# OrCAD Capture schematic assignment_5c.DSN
size A3
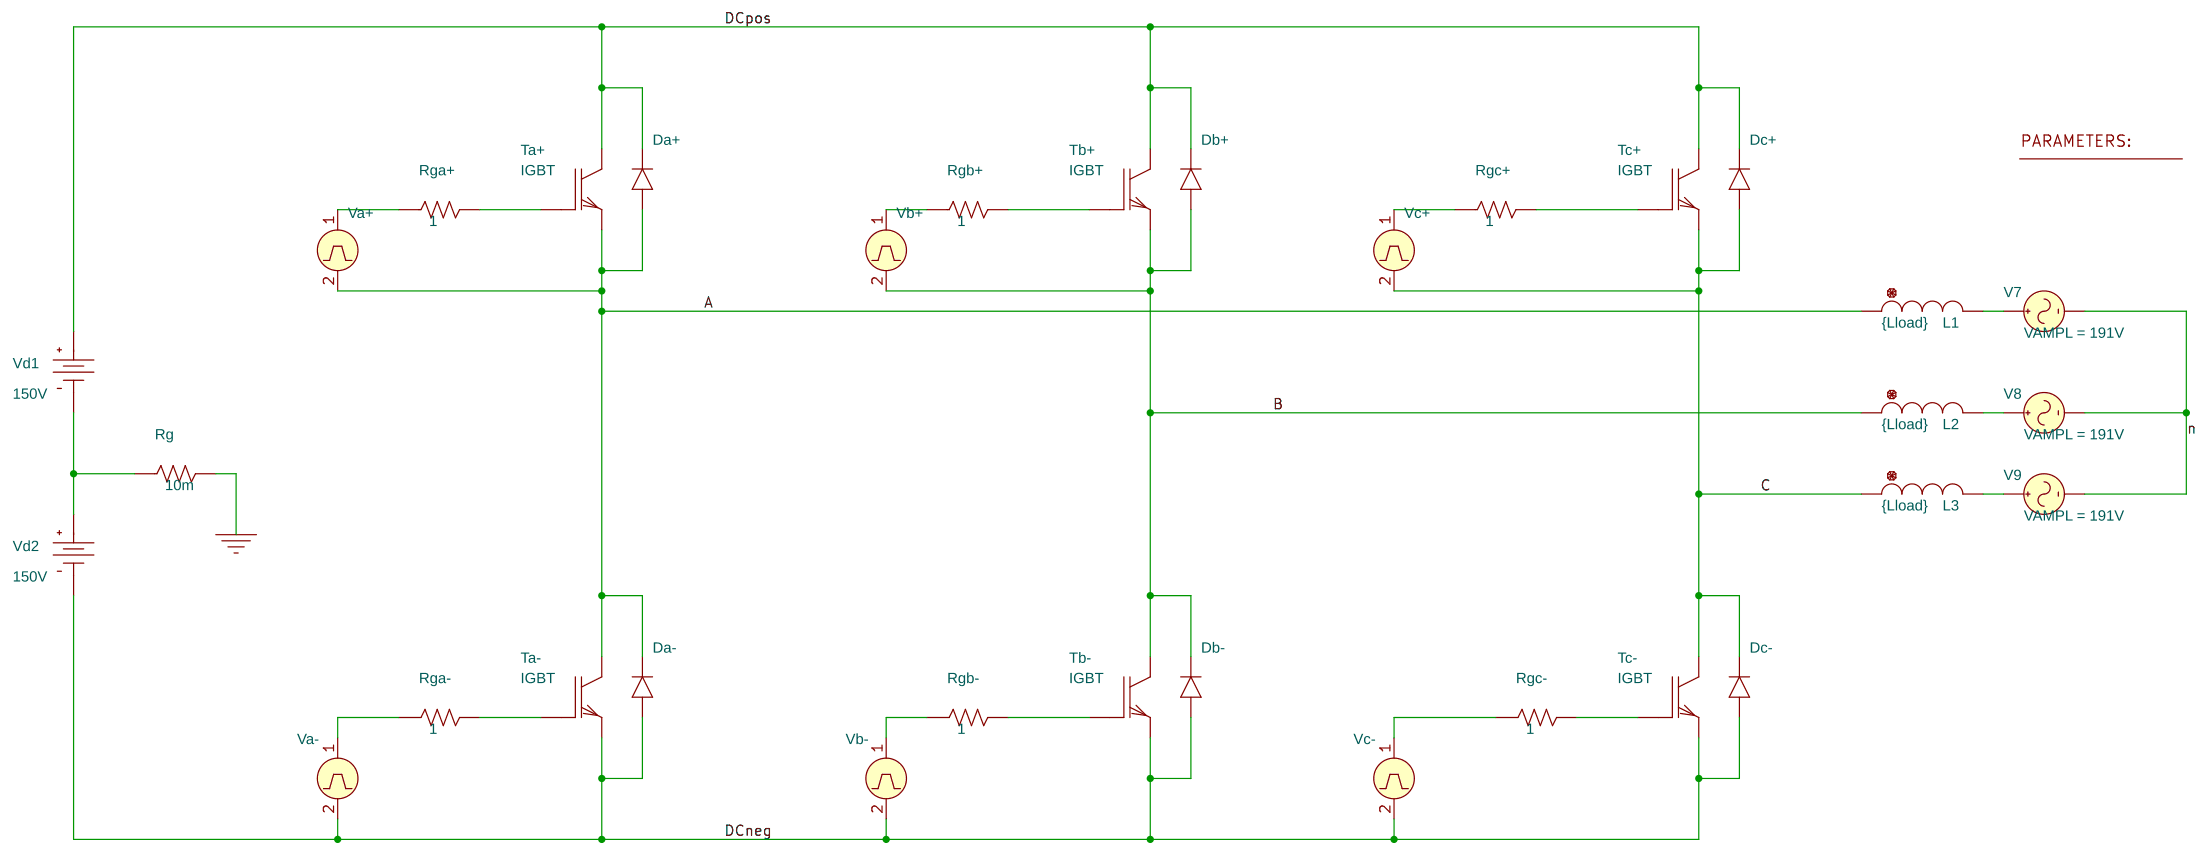
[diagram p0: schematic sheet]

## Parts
1  PARAM
Da+  d
Da-  d
Db+  d
Db-  d
Dc+  d
Dc-  d
L1  {Lload}  [DISC/.350x.175/LS.200x.100/.034]
L2  {Lload}  [DISC/.350x.175/LS.200x.100/.034]
L3  {Lload}  [DISC/.350x.175/LS.200x.100/.034]
Rg  10m  [AX/RC05]
Rga+  1  [AX/RC05]
Rga-  1  [AX/RC05]
Rgb+  1  [AX/RC05]
Rgb-  1  [AX/RC05]
Rgc+  1  [AX/RC05]
Rgc-  1  [AX/RC05]
Ta+  IGBT
Ta-  IGBT
Tb+  IGBT
Tb-  IGBT
Tc+  IGBT
Tc-  IGBT
V7  VSIN
V8  VSIN
V9  VSIN
Va+  VPULSE
Va-  VPULSE
Vb+  VPULSE
Vb-  VPULSE
Vc+  VPULSE
Vc-  VPULSE
Vd1  VDC
Vd2  VDC

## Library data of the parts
1 = PARAM: Lload: 1m; Phi: 0; freq: 50Hz
Da+ Da- Db+ Db- Dc+ Dc- = diode
L1 L2 = L: IC: -7A
L3 = L: IC: 14A
Rg Rga+ Rga- Rgb+ Rgb- Rgc+ Rgc- = R
Ta+ Ta- Tb+ Tb- Tc+ Tc- = CM300DY-24H
V7 = VSIN: FREQ: {freq}; PHASE: {Phi}; VAMPL: 191V; VOFF: 0
V8 = VSIN: FREQ: {freq}; PHASE: {Phi}; TD: {1/(3*freq)}; VAMPL: 191V; VOFF: 0
V9 = VSIN: FREQ: {freq}; PHASE: {Phi}; TD: {2/(3*freq)}; VAMPL: 191V; VOFF: 0
Va+ = VPULSE: PER: {1/freq}; PW: {0.5/freq}; TD: 200n; TF: 200n; TR: 200n; V1: 0; V2: 15
Va- = VPULSE: PER: {1/freq}; PW: {{0.5/freq}+400n}; TD: 0; TF: 200n; TR: 200n; V1: 15; V2: 0
Vb+ = VPULSE: PER: {1/freq}; PW: {0.5/freq}; TD: {1/(3*freq)+200n}; TF: 200n; TR: 200n; V1: 0; V2: 15
Vb- = VPULSE: PER: {1/freq}; PW: {{0.5/freq}+400n}; TD: {1/(3*freq)}; TF: 200n; TR: 200n; V1: 15; V2: 0
Vc+ = VPULSE: PER: {1/freq}; PW: {0.5/freq}; TD: {2/(3*freq)+200n}; TF: 200n; TR: 200n; V1: 0; V2: 15
Vc- = VPULSE: PER: {1/freq}; PW: {{0.5/freq}+400n}; TD: {2/(3*freq)}; TF: 200n; TR: 200n; V1: 15; V2: 0
Vd1 Vd2 = VDC: DC: 150V

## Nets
0: Rg.2
A: Da+.1(A) Da-.2(K) L1.1 Ta+.3(E) Ta-.2(C) Va+.2(-)
B: Db+.1(A) Db-.2(K) L2.1 Tb+.3(E) Tb-.2(C) Vb+.2(-)
C: Dc+.1(A) Dc-.2(K) L3.1 Tc+.3(E) Tc-.2(C) Vc+.2(-)
DCneg: Da-.1(A) Db-.1(A) Dc-.1(A) Ta-.3(E) Tb-.3(E) Tc-.3(E) Va-.2(-) Vb-.2(-) Vc-.2(-) Vd2.1(-)
DCpos: Da+.2(K) Db+.2(K) Dc+.2(K) Ta+.2(C) Tb+.2(C) Tc+.2(C) Vd1.0(+)
n: V7.2(-) V8.2(-) V9.2(-)
N53839: L3.2 V9.1(+)
N53873: L2.2 V8.1(+)
N54065: Rgc-.1 Vc-.1(+)
N54123: Rgb-.1 Vb-.1(+)
N54265: Rgc+.1 Vc+.1(+)
N54365: Rgb+.1 Vb+.1(+)
N54645: Rga+.1 Va+.1(+)
N54715: Rga-.1 Va-.1(+)
N54807: Rga-.2 Ta-.1(G)
N54817: Rga+.2 Ta+.1(G)
N54823: Rgb+.2 Tb+.1(G)
N54833: Rgc+.2 Tc+.1(G)
N54953: Rgb-.2 Tb-.1(G)
N54977: L1.2 V7.1(+)
N55005: Rgc-.2 Tc-.1(G)
N72650: Rg.1 Vd1.1(-) Vd2.0(+)
